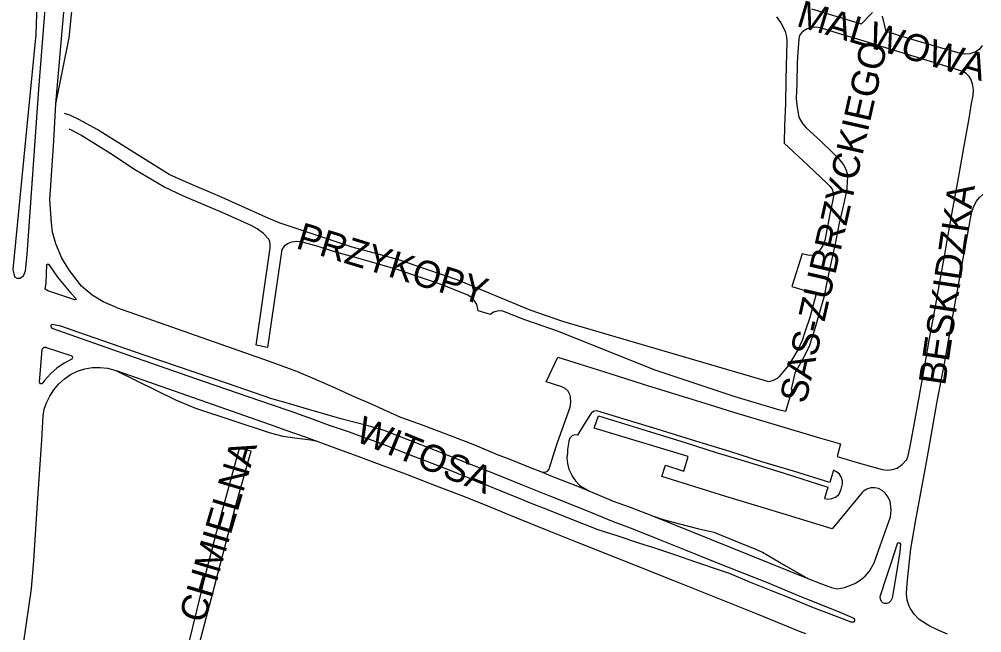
# Model space of a CAD drawing. Extents: x -304109 to -273954, y 21500 to 39796.
# Drawn here: x -293292.6 to -292935.8, y 26504 to 26731.3 of the extents above; entities that cross this region are included whole.
import ezdxf

# ---------------------------------------------------------------- set-up
doc = ezdxf.new("R2010")
doc.units = 0
doc.layers.add('krawedzie_ulic', color=7, linetype='Continuous')
doc.layers.add('nazwy_ulic', color=7, linetype='Continuous')

msp = doc.modelspace()

# ---------------------------------------------------------------- linework, layer by layer
at = {"layer": 'krawedzie_ulic'}
for points in [[(-293251.567, 27102.195), (-293259.977, 27020.441), (-293272.546, 26891.403), (-293284.605, 26772.129), (-293285.75, 26744.42), (-293286.478, 26725.57), (-293289.287, 26696.69), (-293295.004, 26638.518), (-293294.38, 26635.884), (-293293.444, 26635.396), (-293292.299, 26635.298), (-293290.947, 26636.176), (-293290.218, 26638.128), (-293289.594, 26644.079)], [(-293289.594, 26644.079), (-293285.337, 26705.387), (-293280.973, 26760.102), (-293274.419, 26823.619), (-293263.618, 26933.44), (-293256.465, 27016.011), (-293255.841, 27039.915), (-293253.864, 27062.063), (-293249.604, 27102.843)], [(-293279.006, 26699.886), (-293273.388, 26763.793)], [(-293279.006, 26699.886), (-293274.012, 26724.376), (-293271.827, 26746.621), (-293272.035, 26754.231), (-293273.388, 26763.793)], [(-292976.278, 26733.82), (-292980.465, 26729.468), (-292980.721, 26729.545), (-292998.788, 26735.058)], [(-293011.916, 26732.112), (-293010.28, 26729.965), (-293008.98, 26727.601), (-293008.624, 26726.769), (-293008.155, 26724.811), (-293008.066, 26723.111), (-293008.428, 26708.992), (-293008.519, 26699.988), (-293008.846, 26691.897), (-293008.979, 26685.385), (-293000.252, 26677.158), (-292993.111, 26670.369), (-292992.041, 26669.487), (-292991.265, 26668.337), (-292990.85, 26667.028), (-292990.692, 26665.799), (-292990.811, 26664.969), (-292992.191, 26658.447), (-292994.011, 26649.303), (-292994.754, 26647.425), (-292995.852, 26645.73), (-292996.221, 26645.293), (-292997.239, 26644.443), (-292998.464, 26643.932), (-292999.785, 26643.808), (-293000.281, 26643.864), (-293002.395, 26644.357), (-293006.153, 26632.273), (-292997.208, 26629.491), (-292999.564, 26620.775), (-293001.234, 26615.726), (-293002.33, 26612.285), (-293003.959, 26608.813), (-293007.253, 26603.244), (-293008.148, 26602.084), (-293011.062, 26598.739), (-293011.681, 26598.227), (-293013.132, 26597.408), (-293014.737, 26596.957), (-293091.028, 26619.237), (-293103.135, 26623.491), (-293113.284, 26627.663), (-293119.915, 26630.463), (-293125.806, 26632.937), (-293130.294, 26634.71), (-293134.933, 26636.379), (-293142.554, 26638.917), (-293151.476, 26641.979), (-293159.476, 26644.234), (-293169.132, 26646.833), (-293177.721, 26649.72), (-293186.591, 26652.605), (-293195.843, 26655.741), (-293200, 26657.448), (-293217.319, 26665.196), (-293230.887, 26671.078), (-293236.97, 26673.737), (-293250.817, 26682.437), (-293263.734, 26690.382), (-293270.263, 26694.037), (-293273.877, 26695.75), (-293275.849, 26696.382)], [(-292935.586, 26721.532), (-292936.634, 26720.232), (-292937.959, 26719.218), (-292938.308, 26719.025), (-292940.208, 26718.494), (-292942.176, 26718.356), (-292943.11, 26718.43), (-292951.085, 26720.634), (-292963.291, 26724.308), (-292971.164, 26726.673), (-292972.544, 26732.439)], [(-292939.527, 26700.042), (-292938.975, 26703.063), (-292938.83, 26705.094), (-292939.193, 26707.342), (-292939.858, 26709.052), (-292940.435, 26710.107), (-292941.556, 26711.215), (-292942.838, 26711.971), (-292947.145, 26713.313), (-292960.879, 26717.433), (-292970.946, 26720.563), (-292979.406, 26723.12), (-292990.108, 26726.347), (-292995.562, 26728.062), (-292997.206, 26728.353), (-292998.871, 26728.246), (-293000.464, 26727.747), (-293001.709, 26727.024), (-293002.649, 26726.258), (-293003.292, 26725.23), (-293003.568, 26724.049), (-293003.57, 26724.009), (-293004.199, 26715.509), (-293004.372, 26707.191), (-293004.566, 26702.077), (-293004.376, 26699.486), (-293003.759, 26695.623), (-293003.313, 26694.508), (-293002.234, 26692.646), (-293000.829, 26691.015), (-292995.558, 26686.247), (-292990.873, 26681.679), (-292988.72, 26679.511), (-292987.004, 26677.282), (-292986.154, 26675.788), (-292985.672, 26674.138), (-292985.582, 26672.422), (-292985.669, 26671.671), (-292985.823, 26668.185), (-292987.154, 26661.969), (-292988.587, 26655.778), (-292990.235, 26647.576), (-292992.06, 26639.143), (-292993.44, 26632.596), (-292994.252, 26628.623), (-292996.04, 26622.276), (-292997.778, 26616.159), (-292998.875, 26612.895), (-292999.647, 26610.448), (-293001.252, 26607.104), (-293002.934, 26603.912), (-293005.071, 26600.208), (-293006.454, 26594.246), (-293006.047, 26594.148), (-293008.559, 26585.914), (-293010.621, 26586.438), (-293027.231, 26591.422), (-293057.188, 26601.416), (-293092.671, 26615.568), (-293105.145, 26619.966), (-293113.254, 26623.162), (-293114.067, 26623.287), (-293115.472, 26623.185), (-293116.793, 26622.695), (-293117.924, 26621.855), (-293122.486, 26623.271), (-293122.549, 26624.032), (-293122.972, 26625.582), (-293123.764, 26626.98), (-293124.875, 26628.14), (-293126.237, 26628.991), (-293134.627, 26632.414), (-293138.272, 26633.709), (-293144.925, 26635.974), (-293152.062, 26638.44), (-293158.942, 26640.423), (-293167.528, 26642.903), (-293176.064, 26645.281), (-293181.798, 26647.121), (-293186.766, 26648.432), (-293188.548, 26648.8), (-293189.779, 26648.9), (-293191.523, 26648.702), (-293191.687, 26648.661), (-293193.098, 26648.083), (-293194.311, 26647.159), (-293195.243, 26645.953), (-293195.901, 26641.777), (-293200.528, 26609.646), (-293204.76, 26610.47), (-293199.691, 26645.666), (-293199.594, 26646.429), (-293199.579, 26647.981), (-293199.637, 26648.922), (-293200, 26649.8)], [(-293256.482, 26624.526), (-293261.423, 26626.627), (-293265.584, 26629.065), (-293269.434, 26632.381), (-293273.908, 26638.136), (-293276.821, 26642.818), (-293279.005, 26648.085), (-293280.254, 26652.376), (-293280.67, 26655.79), (-293281.19, 26664.415), (-293279.734, 26686.173), (-293279.006, 26699.886)], [(-293096.001, 26565.093), (-293094.583, 26569.938), (-293093.063, 26574.503), (-293088.396, 26587.585), (-293088.094, 26589.405), (-293088.191, 26591.246), (-293088.428, 26592.29), (-293089.148, 26593.508), (-293090.178, 26594.478), (-293091.422, 26595.117), (-293097.233, 26597.007), (-293092.946, 26606.068), (-293085.046, 26603.583), (-293070.953, 26599.185), (-293061.243, 26596.027), (-293051.305, 26593.023), (-293036.805, 26588.578), (-293027.783, 26585.72), (-293012.876, 26581.202), (-292995.981, 26576.164), (-292988.108, 26573.933), (-292989.425, 26569.294), (-292981.908, 26567.086), (-292972.735, 26564.458), (-292970.811, 26564.237), (-292968.882, 26564.415), (-292967.093, 26564.958), (-292965.307, 26566.271), (-292963.785, 26567.882), (-292963.706, 26567.984), (-292963.004, 26569.516), (-292962.097, 26574.406), (-292959.399, 26589.152), (-292957.194, 26601.505), (-292955.111, 26612.991), (-292953.224, 26623.535), (-292951.24, 26634.664), (-292949.498, 26644.164), (-292948.225, 26651.423), (-292946.485, 26660.999), (-292944.671, 26670.983), (-292942.442, 26683.615), (-292940.507, 26694.541), (-292939.527, 26700.042)], [(-292939.527, 26700.042), (-292939.451, 26700.498)], [(-293238.996, 26669.177), (-293249.431, 26675.399), (-293258.645, 26681.453), (-293269.755, 26688.275), (-293273.243, 26690.217), (-293274.055, 26690.577)], [(-293200, 26649.8), (-293201.972, 26651.868), (-293204.429, 26653.668), (-293206.656, 26654.857), (-293217.372, 26659.639), (-293231.639, 26665.687), (-293238.996, 26669.177)], [(-292948.494, 26503.494), (-292951.732, 26504.792), (-292955.287, 26506.561), (-292958.646, 26508.679), (-292959.11, 26509.01), (-292960.861, 26510.918), (-292962.299, 26513.072), (-292962.729, 26513.892), (-292963.418, 26516.045), (-292963.717, 26518.286), (-292963.727, 26518.59), (-292963.447, 26522.255), (-292962.681, 26529.408), (-292962.109, 26535.033), (-292960.199, 26545.882), (-292956.765, 26564.5), (-292955.392, 26571.988), (-292952.308, 26589.688), (-292949.508, 26604.359), (-292946.373, 26622.034), (-292944.238, 26633.495), (-292942.622, 26642.664), (-292940.491, 26654.608), (-292939.976, 26657.486), (-292939.458, 26659.961), (-292938.557, 26662.324), (-292937.705, 26663.887), (-292936.674, 26665.232), (-292935.358, 26666.299)], [(-293271.931, 26627.309), (-293282.023, 26630.626), (-293282.959, 26631.308), (-293282.647, 26633.357), (-293282.335, 26640.379), (-293281.919, 26640.672), (-293281.606, 26640.379), (-293278.381, 26635.698)], [(-293278.381, 26635.698), (-293273.491, 26629.748), (-293271.619, 26627.797), (-293271.411, 26627.407), (-293271.931, 26627.309)], [(-293256.482, 26624.526), (-293199.885, 26604.582), (-293189.847, 26600.883), (-293183.071, 26598.054), (-293175.513, 26594.727), (-293168.845, 26591.645), (-293162.114, 26588.749), (-293156.425, 26586.247), (-293151.234, 26583.889), (-293144.581, 26581.547), (-293137.009, 26578.729), (-293130.278, 26576.109), (-293123.852, 26573.587), (-293115.462, 26570.063), (-293110.669, 26568.242), (-293102.534, 26564.971), (-293098.647, 26563.424)], [(-293199.23, 26588.535), (-293192.283, 26586.143), (-293183.667, 26583.101), (-293178.021, 26581.074), (-293170.243, 26578.363), (-293164.372, 26576.26), (-293159.589, 26574.556), (-293154.624, 26572.597), (-293147.375, 26569.75), (-293141.23, 26567.38), (-293132.536, 26564.061), (-293128.329, 26562.414), (-293120.933, 26559.391), (-293111.931, 26555.668), (-293108.464, 26554.32), (-293102.598, 26551.922), (-293096.76, 26549.651), (-293090.894, 26547.278), (-293083.729, 26544.457), (-293078.145, 26542.184), (-293070.729, 26539.874), (-293063.083, 26537.362), (-293057.476, 26535.521), (-293049.651, 26532.959), (-293041.851, 26530.27), (-293032.37, 26527.11), (-293029.413, 26526.09), (-293021.915, 26522.89), (-293013.857, 26519.694), (-293006.361, 26516.723), (-292998.838, 26513.625), (-292990.781, 26510.53), (-292987.161, 26509.209), (-292984.28, 26508.086), (-292983.979, 26507.994), (-292983.135, 26508.018), (-292982.807, 26508.353), (-292982.78, 26508.871), (-292983.118, 26509.265), (-292989.111, 26511.815), (-293003.085, 26517.434), (-293014.842, 26522.332), (-293024.556, 26526.151), (-293035.24, 26530.37), (-293045.032, 26534.316), (-293054.824, 26538.237), (-293065.049, 26542.332), (-293072.239, 26545.102), (-293082.771, 26549.348), (-293096.081, 26554.667), (-293105.414, 26558.362), (-293117.246, 26563.183), (-293126.477, 26566.802), (-293136.013, 26570.623), (-293145.524, 26574.317), (-293157.304, 26578.94), (-293163.203, 26580.604), (-293172.93, 26583.131), (-293179.344, 26584.98), (-293186.944, 26587.223), (-293191.909, 26588.637), (-293198.977, 26590.675), (-293215.377, 26596.268), (-293246.309, 26606.781), (-293273.698, 26616.367), (-293273.887, 26616.444), (-293277.114, 26617.535), (-293280.446, 26618.241), (-293280.452, 26618.238), (-293280.829, 26617.849), (-293280.85, 26617.306), (-293280.505, 26616.888), (-293251.716, 26606.722), (-293224.44, 26597.223), (-293199.23, 26588.535)], [(-293282.54, 26609.722), (-293273.4, 26606.752), (-293272.936, 26606.402), (-293272.797, 26605.839), (-293273.044, 26605.313), (-293273.077, 26605.282), (-293275.948, 26603.82), (-293278.616, 26602.013), (-293281.04, 26599.89), (-293283.183, 26597.484), (-293283.863, 26596.577), (-293284.199, 26596.238), (-293284.675, 26596.255), (-293284.986, 26596.617), (-293285.009, 26596.842), (-293284.068, 26608.869), (-293283.789, 26609.461), (-293283.222, 26609.788), (-293282.569, 26609.734), (-293282.54, 26609.722)], [(-293290.954, 26499.913), (-293288.057, 26520.268), (-293287.107, 26530.722), (-293285.79, 26552.035), (-293284.209, 26575.395), (-293283.684, 26584.293), (-293283.292, 26586.773), (-293282.512, 26589.16), (-293281.363, 26591.393), (-293281.219, 26591.62), (-293279.743, 26594.019), (-293277.943, 26596.185), (-293275.855, 26598.074), (-293273.52, 26599.649), (-293270.986, 26600.877), (-293268.303, 26601.735), (-293265.526, 26602.204), (-293262.711, 26602.276), (-293259.914, 26601.949), (-293257.191, 26601.229), (-293256.527, 26600.989)], [(-293182.736, 26575.097), (-293186.843, 26576.586), (-293193.624, 26578.89), (-293199.447, 26581.011), (-293256.527, 26600.989)], [(-293256.527, 26600.989), (-293234.663, 26590.285), (-293227.253, 26587.234), (-293199.592, 26578.037), (-293194.888, 26576.757), (-293190.359, 26576.177), (-293184.525, 26575.416), (-293182.736, 26575.097)], [(-293000.308, 26524.118), (-292995.183, 26522.121), (-292991.435, 26520.725), (-292989.321, 26520.283), (-292986.645, 26520.8), (-292984.073, 26521.702), (-292982.85, 26522.289), (-292980.816, 26523.434), (-292979.006, 26524.908), (-292977.475, 26526.67), (-292977.413, 26526.755), (-292975.68, 26529.896), (-292973.434, 26536.246), (-292970.988, 26543.106), (-292969.616, 26546.957), (-292969.401, 26549.362), (-292969.586, 26551.77), (-292969.756, 26552.653), (-292970.49, 26554.269), (-292971.566, 26555.681), (-292972.759, 26556.701), (-292974.035, 26557.404), (-292975.454, 26557.736), (-292976.91, 26557.671), (-292976.961, 26557.661), (-292978.396, 26557.21), (-292979.663, 26556.398), (-292980.078, 26556.01), (-292991.277, 26542.473), (-293009.396, 26547.985), (-293030.648, 26554.465), (-293054.349, 26561.894), (-293053.029, 26566.05), (-293046.174, 26563.888), (-293044.633, 26569.266), (-293079.443, 26579.818), (-293077.871, 26584.306), (-293063.371, 26579.911), (-293045.405, 26574.322), (-293034.269, 26570.818), (-293023.846, 26567.64), (-293009.015, 26563.096), (-292992.832, 26557.925), (-292994.126, 26553.744), (-292992.72, 26553.512), (-292991.304, 26553.679), (-292989.99, 26554.23), (-292988.879, 26555.123), (-292988.669, 26555.362), (-292987.876, 26557.185), (-292987.462, 26559.129), (-292987.404, 26560.127), (-292987.8, 26561.491), (-292988.558, 26562.692), (-292989.62, 26563.635), (-292990.687, 26564.173), (-292992.131, 26559.634), (-293005.587, 26563.833), (-293017.257, 26567.307), (-293029.21, 26571.11), (-293041.773, 26574.959), (-293056.095, 26579.431), (-293071.181, 26584.025), (-293078.443, 26586.209), (-293079.489, 26586.019), (-293080.392, 26585.459), (-293080.573, 26585.278), (-293083.216, 26581.239), (-293085.681, 26577.228), (-293086.615, 26577.312), (-293087.501, 26577.004), (-293087.713, 26576.857), (-293088.438, 26576.034), (-293088.822, 26575.007), (-293088.844, 26574.864), (-293089.322, 26571.936), (-293089.401, 26570.765), (-293089.537, 26568.611), (-293089.322, 26566.696), (-293088.809, 26564.568), (-293087.917, 26562.569), (-293087.612, 26562.055), (-293086.41, 26560.264), (-293084.898, 26558.725), (-293084.383, 26558.314), (-293081.163, 26556.475)], [(-293000.956, 26503.561), (-293003.353, 26504.46), (-293018.629, 26510.756), (-293033.444, 26516.725), (-293048.947, 26522.816), (-293064.119, 26528.961), (-293078.475, 26534.628), (-293085.615, 26537.449), (-293097.37, 26542.169), (-293108.31, 26546.615), (-293118.28, 26550.61), (-293127.766, 26554.406), (-293137.862, 26558.274), (-293149.285, 26562.742), (-293158.004, 26565.933), (-293165.958, 26568.9), (-293175.042, 26572.228), (-293179.412, 26573.891), (-293182.736, 26575.097)], [(-293182.736, 26575.097), (-293182.733, 26575.096)], [(-293225.808, 26500), (-293212.657, 26549.771), (-293210.962, 26556.027), (-293206.642, 26571.291), (-293211.059, 26572.253), (-293215.736, 26555.077), (-293219.495, 26541.495), (-293223.827, 26524.867), (-293226.899, 26512.163), (-293229.881, 26500)], [(-293098.647, 26563.424), (-293097.682, 26563.467), (-293096.814, 26563.893), (-293096.19, 26564.631), (-293096.001, 26565.093)], [(-293098.647, 26563.424), (-293096.134, 26562.424), (-293085.68, 26558.279), (-293079.993, 26556.007), (-293072.368, 26552.782), (-293066.147, 26550.463), (-293057.835, 26547.244)], [(-293096.007, 26565.072), (-293096.001, 26565.093)], [(-293096.001, 26565.093), (-293096, 26565.095)], [(-293057.835, 26547.244), (-293053.91, 26545.95), (-293047.822, 26544.393), (-293040.612, 26542.539), (-293035.161, 26541.231), (-293024.171, 26536.811), (-293020.779, 26535.412), (-293017.056, 26533.888), (-293008.605, 26528.915), (-293000.308, 26524.118)], [(-293057.835, 26547.244), (-293000.308, 26524.118)], [(-292965.881, 26536.763), (-292966.192, 26533.937), (-292967.36, 26526.349), (-292968.996, 26516.748), (-292969.452, 26515.809), (-292970.225, 26515.107), (-292970.94, 26514.801), (-292971.853, 26514.832), (-292972.416, 26515.069), (-292972.96, 26515.574), (-292973.371, 26516.428), (-292973.398, 26517.376), (-292970.934, 26524.923), (-292969.117, 26530.482), (-292967.053, 26537.11), (-292967.016, 26537.157), (-292966.568, 26537.377), (-292966.096, 26537.213), (-292965.881, 26536.763)]]:
    msp.add_lwpolyline(points, dxfattribs=at)

# ---------------------------------------------------------------- texts
at = {"layer": 'nazwy_ulic'}
for s, rotation, p in [('MALWOWA', 343.43135, (-293004.886, 26728.868)), ('SAS-ZUBRZYCKIEGO', 77.15101, (-293001.043, 26588.517)), ('BESKIDZKA', 81.50947, (-292949.361, 26595.294)), ('PRZYKOPY', 342.95566, (-293190.405, 26646.582)), ('WITOSA', 337.79135, (-293168.557, 26575.21)), ('CHMIELNA', 73.51371, (-293223.935, 26507.151))]:
    msp.add_text(s, height=10, rotation=rotation, dxfattribs=at).set_placement(p)

doc.saveas('drawing.dxf')
